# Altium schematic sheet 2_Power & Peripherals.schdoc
size 309 x 223 mm; Symbol: Artery_A4; Device: Artery_A4; Company: Artery Technology; Drawed: SD; Version: 1.0; Page Size: A4; @Project Name: AT-START-F402; @Page Count: 4; @Update Date: 2023-08-18; @Create Date: 2023-05-06; @Schematic Name: AT-START-F402; @Page No: 3; @Page Name: Power & Peripherals
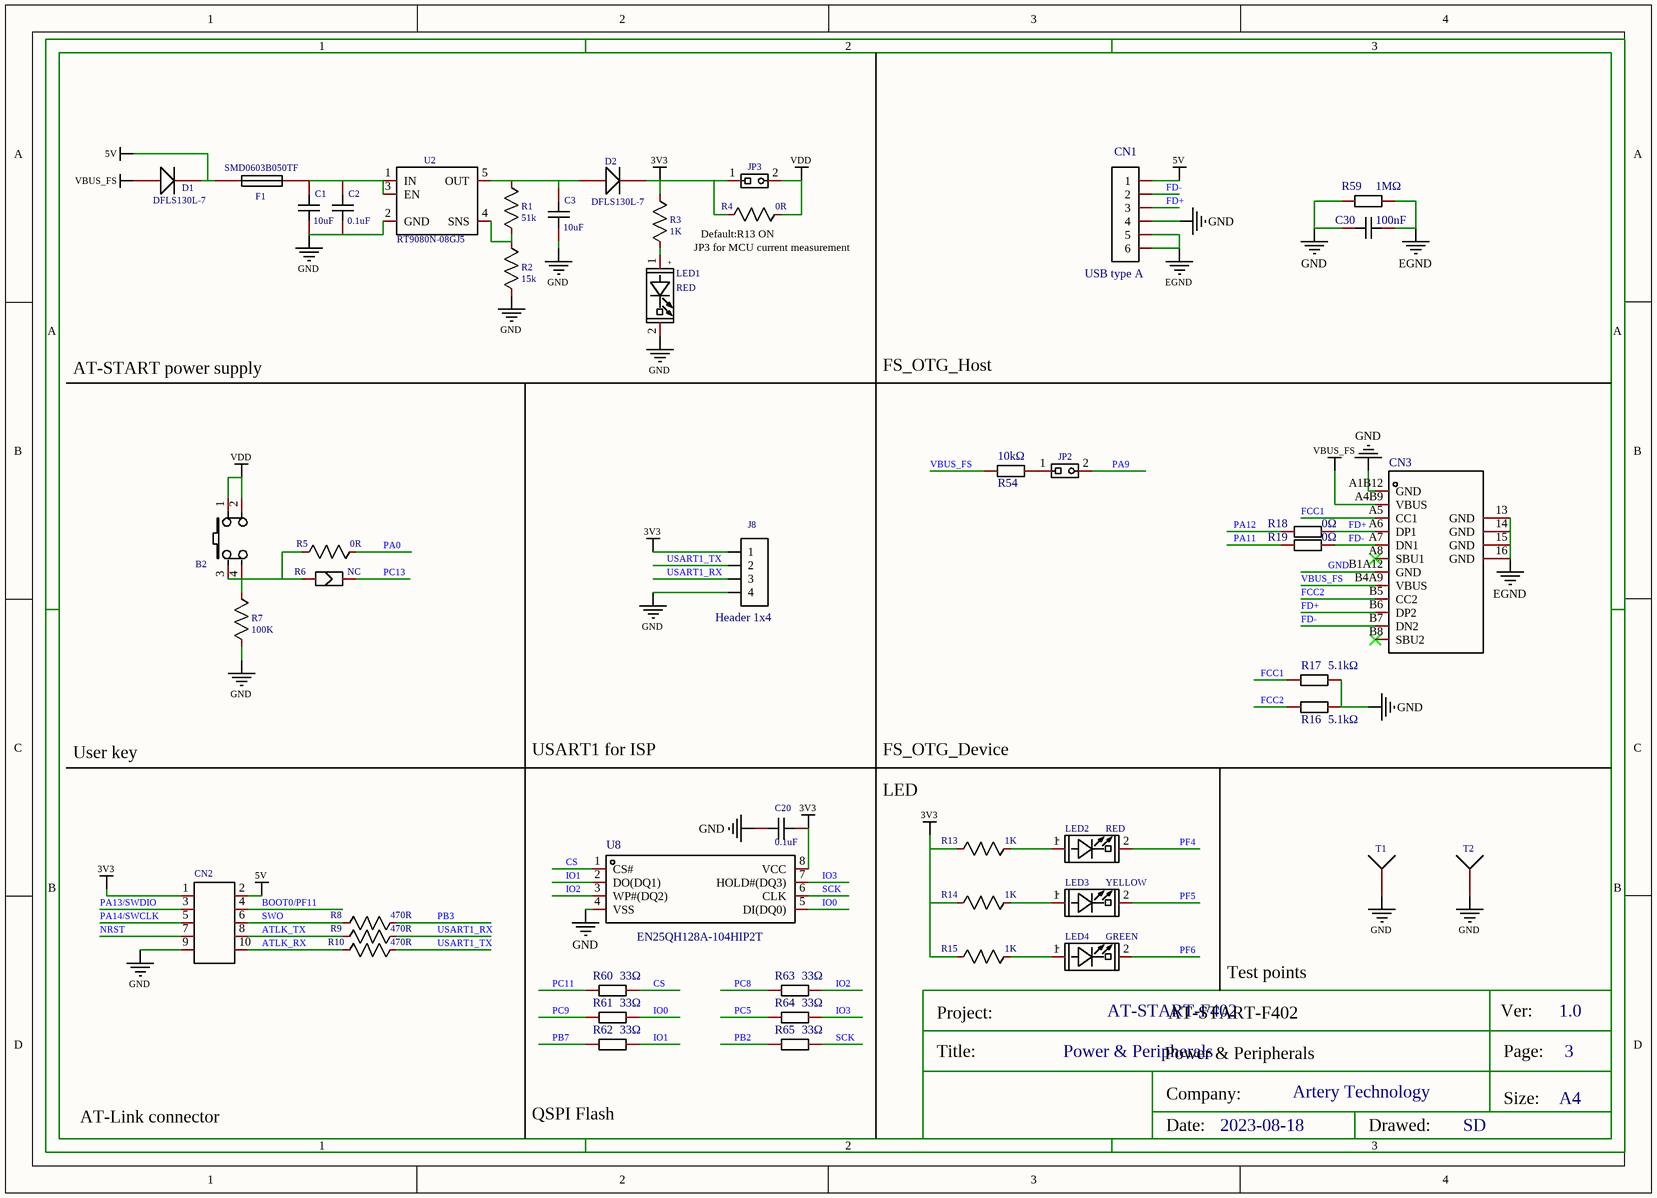
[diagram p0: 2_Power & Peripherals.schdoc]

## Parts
B2  BUTTON_SMT,6.0x6.0x4.5mm  [BUTTON_SMT_6*6*5]  (value not drawn)
C1  10uF  [0603_C-M]
C2  0.1uF  [0603_C-M]
C3  10uF  [0603_C-M]
C20  0.1uF  [0603_C-M]
C30  value 100nF  [C0603]  (hidden comment: CC0603KRX7R9BB104)
CN1  USB type A  [USB-A-TH__USB-AF-90]
CN2  NC(Header 2x5)  [HDR2X5]  (value not drawn)
CN3  TYPEC-304-BCP16  [USB-C-SMD_TYPEC-304-BCP16]  (value not drawn)
D1  DFLS130L-7  [SOD-123]
D2  DFLS130L-7  [SOD-123]
F1  SMD0603B050TF  [R0603]
J8  Header 1x4  [HDR1X4]
JP2  NC(Header 1x2)  [HEADER 1X2]  (value not drawn)
JP3  NC(Header 1x2)  [HEADER 1X2]  (value not drawn)
LED1  RED  [LED0603]
LED2  RED  [LED0603]
LED3  YELLOW  [LED0603]
LED4  GREEN  [LED0603]
R1  51k  [0603_R-M]
R2  15k  [0603_R-M]
R3  1K  [0603_R-M]
R4  0R  [0603_R-M]
R5  0R  [0603_R-M]
R6  NC  [SB-PAD]
R7  100K  [0603_R-M]
R8  470R  [0603_R-M]
R9  470R  [0603_R-M]
R10  470R  [0603_R-M]
R13  1K  [0603_R-M]
R14  1K  [0603_R-M]
R15  1K  [0603_R-M]
R16  value 5.1kΩ  [R0603]  (hidden comment: 0603WAF5101T5E)
R17  value 5.1kΩ  [R0603]  (hidden comment: 0603WAF5101T5E)
R18  value 0Ω  [R0603]  (hidden comment: 0603WAF220JT5E)
R19  value 0Ω  [R0603]  (hidden comment: 0603WAF220JT5E)
R54  value 10kΩ  [R0603]  (hidden comment: 0603WAF1002T5E)
R59  value 1MΩ  [R0603]  (hidden comment: RC0603FR-071ML)
R60  value 33Ω  [R0603]  (hidden comment: 0603WAF330JT5E)
R61  value 33Ω  [R0603]  (hidden comment: 0603WAF330JT5E)
R62  value 33Ω  [R0603]  (hidden comment: 0603WAF330JT5E)
R63  value 33Ω  [R0603]  (hidden comment: 0603WAF330JT5E)
R64  value 33Ω  [R0603]  (hidden comment: 0603WAF330JT5E)
R65  value 33Ω  [R0603]  (hidden comment: 0603WAF330JT5E)
T1  Testpoint  [TESTHOOK]  (value not drawn)
T2  Testpoint  [TESTHOOK]  (value not drawn)
U2  RT9080N-08GJ5  [SOT-23-5]
U8  EN25QH128A-104HIP2T  [SOP-8_L5.3-W5.3-P1.27-LS8.0-BL]

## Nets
3V3: C20.2 CN2.1 D2.2(K) J8.1 JP3.1 R3.1 R4.2 R13.2 R14.2 R15.2 U8.8(VCC)
5V: CN1.1 CN2.2 D1.2(K) F1.1
EGND: C30.2 CN1.SH1(5) CN1.SH2(6) CN3.13(GND) CN3.14(GND) CN3.15(GND) CN3.16(GND) R59.1
GND: C1.2 C2.2 C3.2 C20.1 C30.1 CN1.4 CN2.9 CN3.A1B12(GND) CN3.B1A12(GND) J8.4 LED1.2(CATHODE) R2.1 R7.2 R16.2 R17.2 R59.2 T1.1 T2.1 U2.2(GND) U8.4(VSS)
VBUS_FS: CN3.A4B9(VBUS) CN3.B4A9(VBUS) D1.1(A) R54.2
VDD: B2.1 B2.2 JP3.2 R4.1
ATLK_RX: CN2.10 R10.2
ATLK_TX: CN2.8 R9.2
BOOT0/PF11: CN2.4
CS: R60.2 U8.1(CS#)
FCC1: CN3.A5(CC1) R17.1
FCC2: CN3.B5(CC2) R16.1
FD+: CN1.3 CN3.A6(DP1) CN3.B6(DP2) R18.2
FD-: CN1.2 CN3.A7(DN1) CN3.B7(DN2) R19.2
IO0: R61.2 U8.5(DI(DQ0))
IO1: R62.2 U8.2(DO(DQ1))
IO2: R63.2 U8.3(WP#(DQ2))
IO3: R64.2 U8.7(HOLD#(DQ3))
NRST: CN2.7
PA0: R5.1
PA9: JP2.2
PA11: R19.1
PA12: R18.1
PA13/SWDIO: CN2.3
PA14/SWCLK: CN2.5
PB2: R65.1
PB3: R8.1
PB7: R62.1
PC5: R64.1
PC8: R63.1
PC9: R61.1
PC11: R60.1
PC13: R6.2
PF4: LED2.2(CATHODE)
PF5: LED3.2(CATHODE)
PF6: LED4.2(CATHODE)
SCK: R65.2 U8.6(CLK)
SWO: CN2.6 R8.2
USART1_RX: J8.3 R9.1
USART1_TX: J8.2 R10.1
NetB2_3: B2.3 B2.4 R5.2 R6.1 R7.1
NetC1_1: C1.1 C2.1 F1.2 U2.1(IN) U2.3(EN)
NetC3_1: C3.1 D2.1(A) R1.2 U2.5(OUT)
NetJP2_1: JP2.1 R54.1
NetLED1_1: LED1.1(ANODE) R3.2
NetLED2_1: LED2.1(ANODE) R13.1
NetLED3_1: LED3.1(ANODE) R14.1
NetLED4_1: LED4.1(ANODE) R15.1
NetR1_1: R1.1 R2.2 U2.4(SNS)

Not connected (* = marked no-connect by the designer): CN3 A8(SBU1)* B8(SBU2)*

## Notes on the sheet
- JP3 for MCU current measurement
- (near R4) Default:R13 ON
- AT-START power supply
- FS_OTG_Host
- User key
- USART1 for ISP
- LED
- FS_OTG_Device
- Test points
- AT-START-F402
- Power & Peripherals
- AT-Link connector
- QSPI Flash

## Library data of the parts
B2 = BUTTON_SMT,6.0x6.0x4.5mm: Convert to PCB: yes
C1 C3 = 10uF: Convert to PCB: yes
C2 C20 = 0.1uF: Convert to PCB: yes
C30 = CC0603KRX7R9BB104: 容值:100nF;精度:±10%;额定电压:50V;温度系数:X7R;; Manufacturer: YAGEO(国巨); Add into BOM: yes; Tolerance: ±10%; Voltage Rated: 50V; Temperature Coefficient: X7R
CN1 = USB type A: Convert to PCB: yes
CN2 = NC(Header 2x5): Convert to PCB: yes
CN3 = TYPEC-304-BCP16: 连接器类型:Type-C;标准:USB 3.1;公母:母座;触点数量:16.0;端口数量:1;安装方式:卧贴;额定电流 - 电源:3A;工作温度范围:-25~+85;焊接温度(最大值):260;; Manufacturer: XUNPU(讯普); Add into BOM: yes; Connector Type: Type-C; Gender: 母座; Number of Contacts: 16.0; Number of Ports: 1; Mounting Sytle: 卧贴; Current Rating - Power (Max): 3A; Welding Temperature (Max): 260
D1 D2 = DFLS130L-7: Convert to PCB: yes
F1 = SMD0603B050TF: Convert to PCB: yes
J8 = Header 1x4: Convert to PCB: yes
JP2 JP3 = NC(Header 1x2): Convert to PCB: yes
LED1 LED2 = RED: Convert to PCB: yes
LED3 = YELLOW: Convert to PCB: yes
LED4 = GREEN: Convert to PCB: yes
R1 = 51k: Convert to PCB: yes
R2 = 15k: Convert to PCB: yes
R3 R13-R15 = 1K: Convert to PCB: yes
R4 R5 = 0R: Convert to PCB: yes
R6 = NC: Convert to PCB: yes
R7 = 100K: Convert to PCB: yes
R8-R10 = 470R: Convert to PCB: yes
R16 R17 = 0603WAF5101T5E: 电阻类型:厚膜电阻;阻值:5.1kΩ;精度:±1%;功率:1/10W;温度系数:±100ppm/;最大工作电压:75V;工作温度范围:-55~+155;; Manufacturer: UNI-ROYAL(厚声); Add into BOM: yes; Tolerance: ±1%; Power(Watts): 1/10W; Overload Voltage (Max): 75V
R18 R19 = 0603WAF220JT5E: 电阻类型:厚膜电阻;阻值:22Ω;精度:±1%;功率:100mW;温度系数:±100ppm/;最大工作电压:75V;工作温度范围:-55~+155;; Manufacturer: UNI-ROYAL(厚声); Add into BOM: yes; Tolerance: ±1%; Power(Watts): 100mW; Overload Voltage (Max): 75V
R54 = 0603WAF1002T5E: 电阻类型:厚膜电阻;阻值:10kΩ;精度:±1%;功率:1/10W;温度系数:±100ppm/;最大工作电压:75V;工作温度范围:-55~+155;; Manufacturer: UNI-ROYAL(厚声); Add into BOM: yes; Tolerance: ±1%; Power(Watts): 1/10W; Overload Voltage (Max): 75V
R59 = RC0603FR-071ML: 阻值:1MΩ;精度:±1%;功率:100mW;温度系数:±100ppm/;最大工作电压:75V;工作温度范围:-55~+155;; Manufacturer: YAGEO(国巨); Add into BOM: yes; Tolerance: ±1%; Power(Watts): 100mW; Overload Voltage (Max): 75V
R60-R65 = 0603WAF330JT5E: 电阻类型:厚膜电阻;阻值:33Ω;精度:±1%;功率:100mW;; Manufacturer: UNI-ROYAL(厚声); Add into BOM: yes; Tolerance: ±1%; Power(Watts): 100mW; Temperature Coefficient: ±100ppm/℃; Overload Voltage (Max): 75V
T1 T2 = Testpoint: Convert to PCB: yes
U2 = RT9080N-08GJ5: Convert to PCB: yes
U8 = EN25QH128A-104HIP2T: 接口类型:SPI;存储容量:128Mbit;时钟频率(fc):104MHz;; Manufacturer: ESMT(晶豪); Add into BOM: yes; Interface Type: SPI; Clock Frequency (fc): 104MHz; Supply Voltage: 2.7V~3.6V; Supply Current (Read): 25mA; Supply Current (Program): 28mA; Standby supply current: 20uA; Page Programming Time (Tpp): 800us; Block Erase Time (tBE): 200ms@(64KB); Data Retention - TDR (Year): 20年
